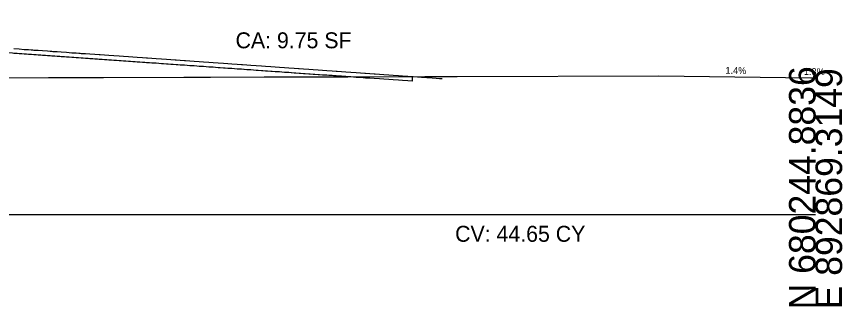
# Model space of a CAD drawing. Extents: x -26 to 4303, y -13 to 10775.
# Drawn here: x 215.7 to 302.8, y 2490.3 to 2520.8 of the extents above; entities that cross this region are included whole.
import ezdxf

# ---------------------------------------------------------------- set-up
doc = ezdxf.new("R2010")
doc.units = 0
for name, color, linetype in [('CONST_LV3', 7, 'Continuous'), ('DTM_X_GROUND', 7, 'Continuous'), ('XS_CELL', 7, 'Continuous'), ('XS_M_SHAPES_EARTHWORK', 7, 'Continuous'), ('XS_P_DR_GRAVEL', 7, 'Continuous'), ('XS_P_TX_FS_BS', 7, 'Continuous'), ('XS_SHEET_EW_TX_AREA', 7, 'Continuous'), ('XS_SHEET_EW_TX_VOLUME', 7, 'Continuous')]:
    doc.layers.add(name, color=color, linetype=linetype)

msp = doc.modelspace()

# ---------------------------------------------------------------- linework, layer by layer
at = {"layer": 'CONST_LV3'}
msp.add_lwpolyline([(215.453, 2517.466), (216, 2517.427), (216.547, 2517.389), (217, 2517.357), (217.453, 2517.326), (218, 2517.287), (218.453, 2517.256), (219, 2517.217), (219.547, 2517.179), (220, 2517.147), (220.453, 2517.116), (221, 2517.077), (221.547, 2517.039), (222, 2517.007), (222.453, 2516.976), (223, 2516.937), (223.453, 2516.906), (224, 2516.867), (224.547, 2516.829), (225, 2516.797), (225.453, 2516.766), (226, 2516.727), (226.547, 2516.689), (227, 2516.657), (227.547, 2516.619), (228, 2516.587), (228.453, 2516.556), (229, 2516.517), (229.547, 2516.479), (230, 2516.447), (230.453, 2516.416), (231, 2516.377), (231.547, 2516.339), (232, 2516.307), (232.453, 2516.276), (233, 2516.237), (233.547, 2516.199), (234, 2516.167), (234.453, 2516.136), (235, 2516.097), (235.453, 2516.066), (236, 2516.027), (236.453, 2515.996), (237, 2515.957), (237.547, 2515.919), (238, 2515.887), (238.453, 2515.856), (239, 2515.817), (239.547, 2515.779), (240, 2515.747), (240.453, 2515.716), (241, 2515.677), (241.547, 2515.639), (242, 2515.607), (242.547, 2515.569), (243, 2515.537), (243.453, 2515.506), (244, 2515.467), (244.453, 2515.436), (245, 2515.397), (245.453, 2515.366), (246, 2515.327), (246.547, 2515.289), (247, 2515.257), (247.547, 2515.219), (248, 2515.187), (248.453, 2515.156), (249, 2515.117), (249.547, 2515.079), (250, 2515.047), (250.453, 2515.016), (251, 2514.977), (251.547, 2514.939), (252, 2514.907), (252.453, 2514.876), (253, 2514.837), (253.547, 2514.799), (254, 2514.767), (254.453, 2514.736), (255, 2514.697), (255.453, 2514.666), (256, 2514.627), (256.453, 2514.596), (257, 2514.557), (257.547, 2514.519), (258, 2514.487), (258.453, 2514.456), (259, 2514.417), (259.547, 2514.379), (260, 2514.347), (260.336, 2514.324), (260.614, 2514.304)], dxfattribs=at)
at = {"layer": 'DTM_X_GROUND'}
msp.add_lwpolyline([(126.483, 2519.853), (129.624, 2520.342), (132.328, 2520.454), (140.446, 2520.825), (142.449, 2520.836), (150.002, 2520.811), (150.026, 2520.811), (153.025, 2520.845), (153.314, 2520.82), (154.313, 2520.72), (155.766, 2520.524), (164.68, 2517.505), (169.665, 2515.248), (196.459, 2514.625), (208.123, 2514.36), (219.103, 2514.434), (224.908, 2514.43), (258.789, 2514.528), (262.204, 2514.527), (283.454, 2514.615), (299.495, 2514.392), (300, 2514.385)], dxfattribs=at)
at = {"layer": 'XS_CELL'}
msp.add_line((150, 2500), (300, 2500), dxfattribs=at)
at = {"layer": 'XS_P_DR_GRAVEL'}
for p, q in [((215.453, 2517.466), (216, 2517.427)), ((216, 2516.927), (215.453, 2516.966)), ((216, 2517.427), (216.547, 2517.389)), ((216.547, 2516.889), (216, 2516.927)), ((216.547, 2517.389), (217, 2517.357)), ((217, 2516.857), (216.547, 2516.889)), ((217, 2517.357), (217.547, 2517.319)), ((217.547, 2516.819), (217, 2516.857)), ((217.547, 2517.319), (218, 2517.287)), ((218, 2516.787), (217.547, 2516.819)), ((218, 2517.287), (218.453, 2517.256)), ((218.453, 2516.756), (218, 2516.787)), ((218.453, 2517.256), (219, 2517.217)), ((219, 2516.717), (218.453, 2516.756)), ((219, 2517.217), (219.453, 2517.186)), ((219.453, 2516.686), (219, 2516.717)), ((219.453, 2517.186), (220, 2517.147)), ((220, 2517.147), (220.453, 2517.116)), ((220.453, 2517.116), (221, 2517.077)), ((221, 2517.077), (221.547, 2517.039)), ((221.547, 2517.039), (222, 2517.007)), ((222, 2517.007), (222.547, 2516.969)), ((222.547, 2516.969), (223, 2516.937)), ((223, 2516.937), (223.453, 2516.906)), ((223.453, 2516.906), (224, 2516.867)), ((224, 2516.867), (224.453, 2516.836)), ((224.453, 2516.836), (225, 2516.797)), ((225, 2516.797), (225.453, 2516.766)), ((225.453, 2516.766), (226, 2516.727)), ((226, 2516.727), (226.547, 2516.689)), ((220, 2516.647), (219.453, 2516.686)), ((220.453, 2516.616), (220, 2516.647)), ((221, 2516.577), (220.453, 2516.616)), ((221.547, 2516.539), (221, 2516.577)), ((222, 2516.507), (221.547, 2516.539)), ((222.547, 2516.469), (222, 2516.507)), ((223, 2516.437), (222.547, 2516.469)), ((223.453, 2516.406), (223, 2516.437)), ((224, 2516.367), (223.453, 2516.406)), ((224.453, 2516.336), (224, 2516.367)), ((225, 2516.297), (224.453, 2516.336)), ((225.453, 2516.266), (225, 2516.297)), ((226, 2516.227), (225.453, 2516.266)), ((226.547, 2516.189), (226, 2516.227)), ((226.547, 2516.689), (227, 2516.657)), ((227, 2516.157), (226.547, 2516.189)), ((227, 2516.657), (227.547, 2516.619)), ((227.547, 2516.119), (227, 2516.157)), ((227.547, 2516.619), (228, 2516.587)), ((228, 2516.087), (227.547, 2516.119)), ((228, 2516.587), (228.453, 2516.556)), ((228.453, 2516.056), (228, 2516.087)), ((228.453, 2516.556), (229, 2516.517)), ((229, 2516.017), (228.453, 2516.056)), ((229, 2516.517), (229.453, 2516.486)), ((229.453, 2515.986), (229, 2516.017)), ((229.453, 2516.486), (230, 2516.447)), ((230, 2515.947), (229.453, 2515.986)), ((230, 2516.447), (230.453, 2516.416)), ((230.453, 2515.916), (230, 2515.947)), ((230.453, 2516.416), (231, 2516.377)), ((231, 2515.877), (230.453, 2515.916)), ((231, 2516.377), (231.547, 2516.339)), ((231.547, 2515.839), (231, 2515.877)), ((231.547, 2516.339), (232, 2516.307)), ((232, 2515.807), (231.547, 2515.839)), ((232, 2516.307), (232.547, 2516.269)), ((232.547, 2516.269), (233, 2516.237)), ((233, 2516.237), (233.453, 2516.206)), ((233.453, 2516.206), (234, 2516.167)), ((234, 2516.167), (234.453, 2516.136)), ((234.453, 2516.136), (235, 2516.097)), ((235, 2516.097), (235.453, 2516.066)), ((235.453, 2516.066), (236, 2516.027)), ((236, 2516.027), (236.453, 2515.996)), ((236.453, 2515.996), (237, 2515.957)), ((237, 2515.957), (237.547, 2515.919)), ((237.547, 2515.919), (238, 2515.887)), ((238, 2515.887), (238.453, 2515.856)), ((238.453, 2515.856), (239, 2515.817)), ((232.547, 2515.769), (232, 2515.807)), ((233, 2515.737), (232.547, 2515.769)), ((233.453, 2515.706), (233, 2515.737)), ((234, 2515.667), (233.453, 2515.706)), ((234.453, 2515.636), (234, 2515.667)), ((235, 2515.597), (234.453, 2515.636)), ((235.453, 2515.566), (235, 2515.597)), ((236, 2515.527), (235.453, 2515.566)), ((236.453, 2515.496), (236, 2515.527)), ((237, 2515.457), (236.453, 2515.496)), ((237.547, 2515.419), (237, 2515.457)), ((238, 2515.387), (237.547, 2515.419)), ((238.453, 2515.356), (238, 2515.387)), ((239, 2515.317), (238.453, 2515.356)), ((239, 2515.817), (239.453, 2515.786)), ((239.453, 2515.286), (239, 2515.317)), ((239.453, 2515.786), (240, 2515.747)), ((240, 2515.247), (239.453, 2515.286)), ((240, 2515.747), (240.453, 2515.716)), ((240.453, 2515.216), (240, 2515.247)), ((240.453, 2515.716), (241, 2515.677)), ((241, 2515.177), (240.453, 2515.216)), ((241, 2515.677), (241.547, 2515.639)), ((241.547, 2515.139), (241, 2515.177)), ((241.547, 2515.639), (242, 2515.607)), ((242, 2515.107), (241.547, 2515.139)), ((242, 2515.607), (242.547, 2515.569)), ((242.547, 2515.069), (242, 2515.107)), ((242.547, 2515.569), (243, 2515.537)), ((243, 2515.037), (242.547, 2515.069)), ((243, 2515.537), (243.453, 2515.506)), ((243.453, 2515.006), (243, 2515.037)), ((243.453, 2515.506), (244, 2515.467)), ((244, 2514.967), (243.453, 2515.006)), ((244, 2515.467), (244.453, 2515.436)), ((244.453, 2514.936), (244, 2514.967)), ((244.453, 2515.436), (245, 2515.397)), ((245, 2515.397), (245.547, 2515.359)), ((245.547, 2515.359), (246, 2515.327)), ((246, 2515.327), (246.547, 2515.289)), ((246.547, 2515.289), (247, 2515.257)), ((247, 2515.257), (247.547, 2515.219)), ((247.547, 2515.219), (248, 2515.187)), ((248, 2515.187), (248.453, 2515.156)), ((248.453, 2515.156), (249, 2515.117)), ((249, 2515.117), (249.453, 2515.086)), ((249.453, 2515.086), (250, 2515.047)), ((250, 2515.047), (250.453, 2515.016)), ((250.453, 2515.016), (251, 2514.977)), ((251, 2514.977), (251.547, 2514.939)), ((245, 2514.897), (244.453, 2514.936)), ((245.547, 2514.859), (245, 2514.897)), ((246, 2514.827), (245.547, 2514.859)), ((246.547, 2514.789), (246, 2514.827)), ((247, 2514.757), (246.547, 2514.789)), ((247.547, 2514.719), (247, 2514.757)), ((248, 2514.687), (247.547, 2514.719)), ((248.453, 2514.656), (248, 2514.687)), ((249, 2514.617), (248.453, 2514.656)), ((249.453, 2514.586), (249, 2514.617)), ((250, 2514.547), (249.453, 2514.586)), ((250.453, 2514.516), (250, 2514.547)), ((251, 2514.477), (250.453, 2514.516)), ((251.547, 2514.439), (251, 2514.477)), ((251.547, 2514.939), (252, 2514.907)), ((252, 2514.407), (251.547, 2514.439)), ((252, 2514.907), (252.547, 2514.869)), ((252.547, 2514.369), (252, 2514.407)), ((252.547, 2514.869), (253, 2514.837)), ((253, 2514.337), (252.547, 2514.369)), ((253, 2514.837), (253.453, 2514.806)), ((253.453, 2514.306), (253, 2514.337)), ((253.453, 2514.806), (254, 2514.767)), ((254, 2514.267), (253.453, 2514.306)), ((254, 2514.767), (254.453, 2514.736)), ((254.453, 2514.236), (254, 2514.267)), ((254.453, 2514.736), (255, 2514.697)), ((255, 2514.197), (254.453, 2514.236)), ((255, 2514.697), (255.453, 2514.666)), ((255.453, 2514.166), (255, 2514.197)), ((255.453, 2514.666), (256, 2514.627)), ((256, 2514.127), (255.453, 2514.166)), ((256, 2514.627), (256.453, 2514.596)), ((256.453, 2514.096), (256, 2514.127)), ((256.453, 2514.596), (257, 2514.557)), ((257, 2514.057), (256.453, 2514.096)), ((257, 2514.557), (257.472, 2514.524)), ((257.472, 2514.524), (257.472, 2514.024)), ((257.472, 2514.024), (257, 2514.057))]:
    msp.add_line(p, q, dxfattribs=at)
at = {"layer": 'XS_SHEET_EW_TX_AREA'}
msp.add_lwpolyline([(168.925, 2520.47), (180, 2517.701), (188.689, 2514.805), (196.459, 2514.625), (202.291, 2514.493), (208.123, 2514.36), (213.613, 2514.397), (224.908, 2514.43), (241.848, 2514.479), (250.675, 2514.487), (212.773, 2517.153), (195.727, 2518.346), (182.052, 2519.299), (176.802, 2519.588), (171.025, 2519.989)], close=True, dxfattribs=at)

# ---------------------------------------------------------------- texts
at = {"layer": 'XS_CELL'}
for s, p in [('N 680244.8836', (300, 2490)), ('E 892869.3149', (302.8, 2490))]:
    msp.add_text(s, height=2.8, rotation=90, dxfattribs=at).set_placement(p)
at = {"layer": 'XS_M_SHAPES_EARTHWORK'}
msp.add_text('CV: 44.65 CY', height=1.68, dxfattribs=at).set_placement((261.986, 2497.12))
at = {"layer": 'XS_P_TX_FS_BS'}
for s, rotation, p in [('1.4%', 359.20397, (290.496, 2514.817)), ('1.3%', 359.22977, (298.769, 2514.702))]:
    msp.add_text(s, height=0.72, rotation=rotation, dxfattribs=at).set_placement(p)
at = {"layer": 'XS_SHEET_EW_TX_VOLUME'}
msp.add_text('CA: 9.75 SF', height=1.68, dxfattribs=at).set_placement((238.826, 2517.5))

doc.saveas('drawing.dxf')
